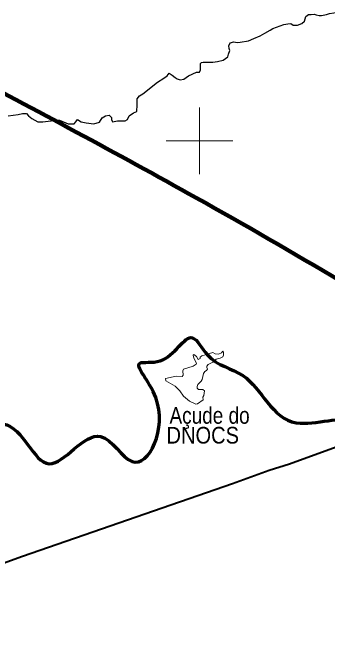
# Model space of a CAD drawing. Extents: x 553962 to 842807, y 8883888 to 9032388.
# Drawn here: x 594396 to 603837, y 8960165 to 8978853 of the extents above; entities that cross this region are included whole.
import ezdxf
from ezdxf.enums import TextEntityAlignment as Align

# ---------------------------------------------------------------- set-up
doc = ezdxf.new("R2010")
doc.units = 0
doc.header["$LTSCALE"] = 200
for name, color, linetype, lineweight in [('12', 7, 'Continuous', 25), ('2', 7, 'Continuous', 13), ('22', 7, 'Continuous', 13), ('24', 7, 'Continuous', 25), ('51', 7, 'Continuous', 70), ('9', 7, 'Continuous', 90)]:
    doc.layers.add(name, color=color, linetype=linetype, lineweight=lineweight)
doc.layers.add('50', color=7, linetype='Continuous')

msp = doc.modelspace()

# ---------------------------------------------------------------- linework, layer by layer
at = {"layer": '12', "lineweight": 40}
msp.add_lwpolyline([(593118.3, 8961975.5), (594700.8, 8962547.5), (600985.5, 8964722.4), (602091.6, 8965119.9), (602697.1, 8965318.9), (609861, 8967928.7)], dxfattribs=at)
at = {"layer": '2'}
for p, q in [((600000, 8974000), (600000, 8976000)), ((599000, 8975000), (601000, 8975000))]:
    msp.add_line(p, q, dxfattribs=at)
at = {"layer": '22'}
for points in [[(599809.1, 8968571.9), (599807.2, 8968579.6), (599825.8, 8968589.3), (599913, 8968531.8), (599957.7, 8968446.1), (600016.8, 8968470.3), (600024, 8968513.4), (600074.7, 8968549.4), (600397.5, 8968653.6), (600470.2, 8968613.3), (600565, 8968605), (600658.8, 8968647.2), (600702.7, 8968690.5), (600704.6, 8968688.3)], [(600704.6, 8968688.3), (600721.8, 8968668.3), (600716.4, 8968577.4), (600697.2, 8968526.2), (600615.2, 8968484), (600495.5, 8968451.8), (600399.8, 8968360.6), (600257.6, 8968290.3), (600215.3, 8968243.9), (600215.2, 8968203.3), (600238.2, 8968158.5), (600215, 8968118.4), (600157.8, 8968080.1), (600117.6, 8968027.2), (600078.7, 8967845.6), (600049.3, 8967791.2), (599953.8, 8967693.5), (599926.3, 8967638.5), (599930.5, 8967583.1), (599969.1, 8967544.5), (600104.8, 8967540.5), (600151.1, 8967502.5), (600134.3, 8967366.4), (600104.7, 8967317.5), (600109.2, 8967237.7)], [(598979.7, 8967874.9), (598979.6, 8967875.5), (599301.7, 8967946.2), (599480.2, 8967933.8), (599509.8, 8967969.9), (599501.3, 8968101.1), (599516.3, 8968150.1), (599811.5, 8968247.9), (599904.8, 8968303.2), (599909, 8968337.3), (599832.8, 8968479.3), (599809.1, 8968571.9)], [(599516.6, 8967344.8), (599411.9, 8967506.8), (599276.3, 8967640.2), (598993.8, 8967806), (598979.7, 8967874.9)], [(600109.2, 8967237.7), (599943.1, 8967117.9), (599886.4, 8967105.1), (599701.2, 8967194.2), (599516.6, 8967344.8)]]:
    msp.add_lwpolyline(points, dxfattribs=at)
at = {"layer": '24'}
for points in [[(602527.9, 8978491.8), (602650.6, 8978515.2), (602738.6, 8978522.5), (602804.6, 8978471.2), (602936.6, 8978471.2), (603068.6, 8978522.5), (603142, 8978588.6), (603186, 8978735.3), (603266.7, 8978786.7), (603347.3, 8978794), (603435.3, 8978801.4), (603494, 8978779.4), (603582, 8978764.7), (603655.3, 8978764.7), (603809.3, 8978786.7)], [(603809.3, 8978786.7), (603897.3, 8978823.4), (604022, 8978838.1), (604139.3, 8978852.8), (604271.3, 8978823.4), (604432.7, 8978786.7), (604550, 8978757.3), (604975, 8978572.4)], [(594271.7, 8975755.3), (594567.8, 8975788.2), (594699.4, 8975821.1), (594814.5, 8975821.1), (594880.3, 8975755.3), (594979, 8975673), (595160, 8975574.2), (595308.1, 8975574.2), (595719.3, 8975623.6), (595801.6, 8975623.6), (596064.8, 8975508.3), (596163.5, 8975508.3), (596245.7, 8975508.3), (596295.1, 8975574.2), (596344.4, 8975640), (596459.6, 8975574.2), (596607.7, 8975541.3), (596838, 8975508.3), (597002.5, 8975557.7), (597084.7, 8975689.4), (597183.4, 8975755.3), (597298.6, 8975771.7), (597364.4, 8975705.9), (597364.4, 8975640), (597397.3, 8975574.2), (597545.3, 8975607.1), (597627.6, 8975607.1), (597775.7, 8975607.1), (597841.5, 8975640), (597890.8, 8975755.3), (598022.4, 8975837.6), (598121.1, 8975887), (598137.6, 8976084.5), (598137.6, 8976265.6), (598203.4, 8976347.9), (598302.1, 8976413.7), (598746.2, 8976759.4), (598932.5, 8976878.8), (599027.9, 8976952.2), (599093.9, 8977032.9), (599181.9, 8976974.2), (599269.9, 8976900.8), (599328.6, 8976864.1), (599416.6, 8976827.4), (599526.6, 8976856.8), (599665.9, 8976952.2), (599907.9, 8977062.2), (600003.2, 8977062.2), (600032.6, 8977135.6), (600032.6, 8977238.3), (600032.6, 8977319.1), (600061.9, 8977348.4), (600113.2, 8977363.1), (600274.6, 8977363.1), (600399.2, 8977363.1), (600538.6, 8977377.8), (600707.2, 8977421.8), (600846.6, 8977524.5), (600868.6, 8977605.3), (600912.6, 8977708), (600890.6, 8977774), (600883.2, 8977854.8), (600919.9, 8977942.8), (601029.9, 8977972.2), (601125.3, 8977950.2), (601220.6, 8977957.5), (601469.9, 8978001.5), (601623.9, 8978067.6), (601821.9, 8978155.6), (601961.3, 8978236.3), (602115.3, 8978317.1), (602196, 8978368.4), (602527.9, 8978491.8)]]:
    msp.add_lwpolyline(points, dxfattribs=at)
at = {"layer": '51'}
msp.add_spline([(592045.3, 8966365.8), (592105.7, 8965948), (594116, 8966514), (595498, 8965319.1), (597037.2, 8966136.7), (597979.5, 8965382), (598692.6, 8967300.2), (598221.4, 8968337.9), (598818.2, 8968400.8), (599792, 8969092.6), (600231.7, 8968589.5), (601299.7, 8967960.6), (602901.6, 8966545.5), (604566.4, 8966482.6), (604745.5, 8965696.5), (605405.1, 8964973.2), (606347.4, 8965067.5), (606598.7, 8965916.6), (607760.9, 8966168.1), (606881.4, 8967363.1), (606818.6, 8968966.8), (608671.8, 8969249.8), (610641.3, 8969878.8), (611740.7, 8970224.7), (613019.2, 8969721.5), (613813.8, 8969815.9), (614966.7, 8967143), (615657.7, 8967897.7), (616819.9, 8967551.8), (618578.9, 8965130.4), (619826, 8965948), (620642.7, 8965633.6), (621804.8, 8965948), (623218.3, 8965539.2), (624506.2, 8966105.2), (626233.7, 8967551.8), (628149.5, 8965483.5), (628181, 8964376.2), (628353.9, 8962908.5), (629301.3, 8963064.1), (629808.6, 8963286.1), (631079.5, 8963482.7), (632397.9, 8963531.7), (633735.2, 8964126.9), (635403.4, 8963798.6), (639270.5, 8963331.4), (641424.7, 8962981.9), (643321.9, 8962962.5), (643886.9, 8964740.5), (644763.1, 8965131.4), (647540.5, 8964979.2), (649340.2, 8965613.4), (651021.3, 8966658.1), (652098.8, 8967969.1), (652112.8, 8969176.8), (652061.5, 8969848.1), (652848.6, 8969790.3), (652905.5, 8971456.6), (655366.6, 8972918.5), (655467.9, 8971938.7), (654952.1, 8970029.5), (655937.5, 8968195.9), (657437.3, 8968728.9), (657964, 8969442.1), (658605, 8970350.9), (659181.8, 8970558.1), (659395.9, 8969769.5), (660070.2, 8969323), (660146.3, 8968426.2), (660105.6, 8967692), (661532.3, 8968708.4), (662385.2, 8969131.8), (663773.8, 8967258.4)], degree=3, dxfattribs=at)
at = {"layer": '9'}
msp.add_spline([(592698.5, 8977198.4), (599903.5, 8973292.7), (608459.2, 8968138.2), (612674.8, 8965332.6), (616842, 8962096.4), (620005, 8958671.2), (621134, 8957974.7), (621473.4, 8956805.3), (621586.2, 8956597.5)], degree=3, dxfattribs=at)

# ---------------------------------------------------------------- texts
at = {"layer": '50'}
for s, width, p in [('Açude do', 0.85, (600302.7, 8966516.8)), ('DNOCS', 0.9, (600098, 8965922.9))]:
    msp.add_text(s, height=500, dxfattribs=dict(at, width=width)).set_placement(p, align=Align.CENTER)

doc.saveas('drawing.dxf')
